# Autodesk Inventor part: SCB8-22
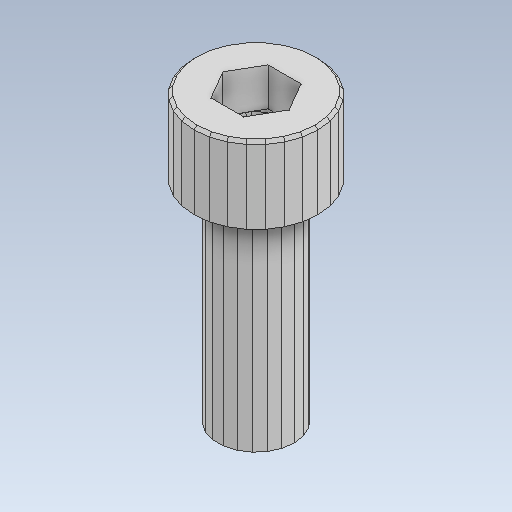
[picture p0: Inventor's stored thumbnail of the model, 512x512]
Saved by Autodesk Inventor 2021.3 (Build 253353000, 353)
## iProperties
Created: 2022-02
Part Number: SCB8-22
Material: 一般
Document SubType Name: Modeling
Designer: kengo
Density: 1 g/cm^3
Appearance: 既定
Author: kengo
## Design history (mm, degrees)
feature "SCB8-22"
node "ソリッド1"
